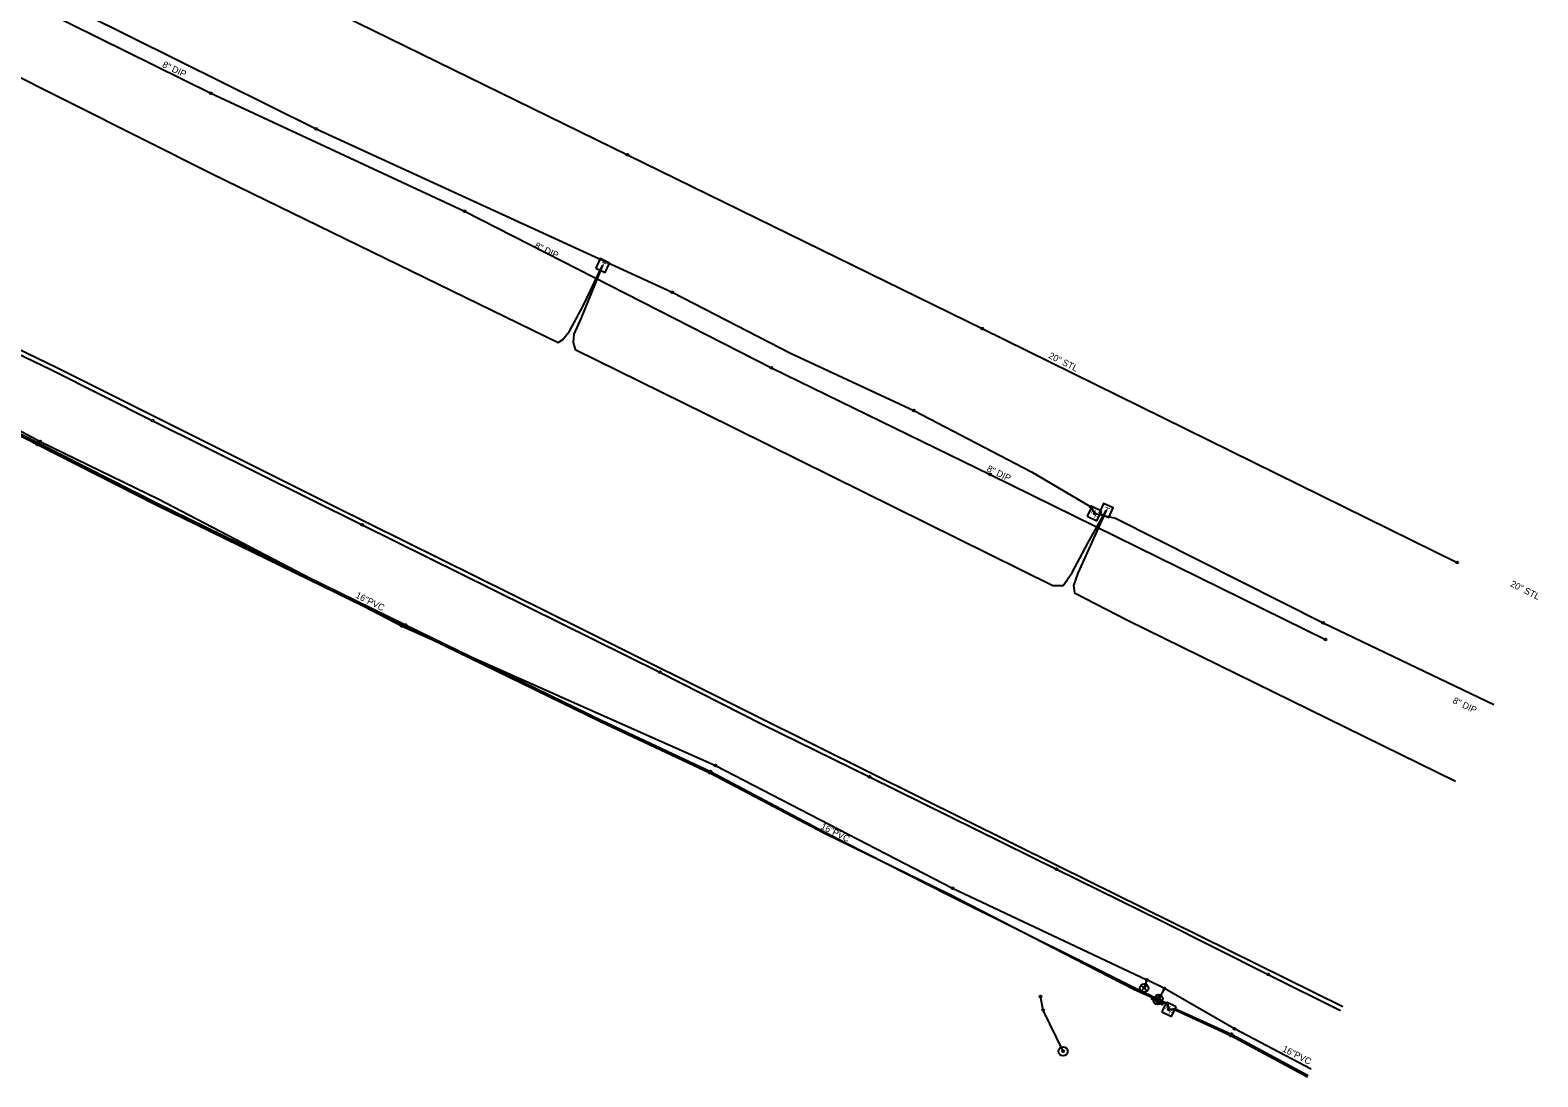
# Model space of a CAD drawing. Extents: x 2244485 to 2250986, y 199568 to 203007.
# Drawn here: x 2250182 to 2250986, y 199568 to 200126 of the extents above; entities that cross this region are included whole.
import ezdxf

# ---------------------------------------------------------------- set-up
doc = ezdxf.new("R2010")
doc.units = 0
for name, color, linetype in [('Default', 7, 'Continuous'), ('Exist Utilities Gas UG Line SUE LOS B', 7, 'Continuous'), ('Exist Utilities Gas UG Line SUE LOS B Text', 7, 'Continuous'), ('Exist Utilities Other Pole CELL', 7, 'Continuous'), ('Exist Utilities Power UG Cable SUE LOS B', 7, 'Continuous'), ('Exist Utilities Sanitary Sewer Forced Main SUE LOS B', 7, 'Continuous'), ('Exist Utilities Sanitary Sewer Forced Main SUE LOS B Text', 7, 'Continuous'), ('Exist Utilities Telephone Hand Hole CELL', 7, 'Continuous'), ('Exist Utilities Telephone Pedestal CELL', 7, 'Continuous'), ('Exist Utilities Telephone UG Cable SUE LOS C', 7, 'Continuous'), ('Exist Utilities Telephone UG FO SUE LOS B', 7, 'Continuous'), ('Exist Utilities Telephone UG FO SUE LOS C', 7, 'Continuous'), ('Exist Utilities Water Fire Hydrant CELL', 7, 'Continuous'), ('Exist Utilities Water UG Line SUE LOS B', 7, 'Continuous'), ('Exist Utilities Water UG Line SUE LOS B Text', 7, 'Continuous'), ('Exist Utilities Water Valve CELL', 7, 'Continuous')]:
    doc.layers.add(name, color=color, linetype=linetype)

# ---------------------------------------------------------------- blocks, each defined once
blk = doc.blocks.new('SurveyPointCell')
at = {"layer": 'Default'}
for p, q in [((-0.5, 0), (0.5, 0)), ((0, -0.5), (0, 0.5))]:
    blk.add_line(p, q, dxfattribs=at)
blk.add_circle((0, 0), 0.5, dxfattribs=at)

msp = doc.modelspace()

# ---------------------------------------------------------------- linework, layer by layer
at = {"layer": 'Exist Utilities Gas UG Line SUE LOS B'}
msp.add_lwpolyline([(2249287.36, 200663.03), (2249402.68, 200604.16), (2249525.39, 200542.56), (2249637.28, 200487.84), (2249753.55, 200430.72), (2249877.93, 200369.52), (2249979.08, 200317.76), (2250124.48, 200245.55), (2250172.44, 200224.83), (2250356.61, 200130.32), (2250500.51, 200059.93), (2250689.7, 199967.14), (2250942.92, 199842.48)], dxfattribs=at)
at = {"layer": 'Exist Utilities Other Pole CELL'}
msp.add_circle((2250732.8, 199581.7), 2.46, dxfattribs=at)
at = {"layer": 'Exist Utilities Power UG Cable SUE LOS B'}
msp.add_lwpolyline([(2250732.85, 199581.76), (2250722.22, 199603.73), (2250720.73, 199610.94)], dxfattribs=at)
at = {"layer": 'Exist Utilities Sanitary Sewer Forced Main SUE LOS B'}
msp.add_lwpolyline([(2249217.76, 200621.23), (2249370.62, 200544.89), (2249544.88, 200455.15), (2249705.6, 200378.34), (2249875.84, 200294.33), (2250020.48, 200224.47), (2250112.79, 200177.26), (2250158.33, 200152.06), (2250278.35, 200092.68), (2250413.6, 200029.72), (2250577.23, 199946.2), (2250693.92, 199889.36), (2250872.7, 199801.35)], dxfattribs=at)
at = {"layer": 'Exist Utilities Telephone Hand Hole CELL'}
for p, q in [((2250748.13, 199872.28), (2250745.7, 199867.09)), ((2250753.31, 199869.85), (2250748.13, 199872.28)), ((2250745.7, 199867.09), (2250750.89, 199864.67)), ((2250749.51, 199868.47), (2250749.51, 199868.47)), ((2250750.89, 199864.67), (2250753.31, 199869.85)), ((2250787.9, 199607.88), (2250785.43, 199602.72)), ((2250793.06, 199605.41), (2250787.9, 199607.88)), ((2250790.59, 199600.25), (2250793.06, 199605.41)), ((2250785.43, 199602.72), (2250790.59, 199600.25)), ((2250789.24, 199604.06), (2250789.24, 199604.06))]:
    msp.add_line(p, q, dxfattribs=at)
at = {"layer": 'Exist Utilities Telephone Pedestal CELL'}
for p, q in [((2250487.21, 200000.87), (2250487.21, 200000.87)), ((2250755.76, 199870.22), (2250755.76, 199870.22))]:
    msp.add_line(p, q, dxfattribs=at)
for points in [[(2250483.54, 199999.49), (2250488.59, 199997.09), (2250490.99, 200002.14), (2250485.94, 200004.54), (2250483.54, 199999.49)], [(2250752.13, 199868.73), (2250757.25, 199866.48), (2250759.51, 199871.6), (2250754.39, 199873.85), (2250752.13, 199868.73)]]:
    msp.add_lwpolyline(points, dxfattribs=at)
at = {"layer": 'Exist Utilities Telephone UG Cable SUE LOS C'}
msp.add_lwpolyline([(2250126.32, 200126.28), (2250278.97, 200049.73), (2250463.49, 199959.77), (2250466.08, 199961.32), (2250469.53, 199965.87), (2250476.77, 199979), (2250487.21, 200000.87), (2250475.74, 199972.84), (2250471.96, 199964.26), (2250471.55, 199959.69), (2250472.59, 199956.11), (2250541.57, 199922.06), (2250727.39, 199830.08), (2250732.79, 199830.2), (2250737.4, 199836.65), (2250745.95, 199852.74), (2250755.76, 199870.22), (2250740.73, 199836.71), (2250738.31, 199830.15), (2250738.96, 199826.31), (2250767.12, 199811.71), (2250942.02, 199725.84)], dxfattribs=at)
at = {"layer": 'Exist Utilities Telephone UG FO SUE LOS B'}
for points in [[(2249321.49, 200578.44), (2249387.5, 200544.86), (2249454.17, 200513.32), (2249518.8, 200482.82), (2249583.28, 200449.94), (2249649.27, 200415.89), (2249731.67, 200374.67), (2249920.99, 200280.45), (2250071.25, 200205.24), (2250113.04, 200184.93), (2250117.77, 200182.84), (2250185.79, 200147.71), (2250334.49, 200073.65), (2250524.31, 199986.53), (2250587.45, 199954.07), (2250653.24, 199923.49), (2250715.98, 199890.78), (2250747.66, 199872.17), (2250749.65, 199868.58), (2250760.75, 199866.03), (2250871.46, 199810.27), (2250962.45, 199766.7)], [(2249319.08, 200376.82), (2249375.45, 200350.06), (2249435.96, 200321), (2249525.24, 200277.08), (2249685.23, 200197.6), (2249751.73, 200164.33), (2249867.18, 200107.28), (2249992.37, 200042.44), (2250002.65, 200033.19), (2250015.25, 200027.15), (2250029.09, 200026.7), (2250139.17, 199971.22), (2250192.89, 199945.32), (2250247.36, 199918.05), (2250358.97, 199862.45), (2250517.75, 199783.98), (2250572.3, 199756.11), (2250629.61, 199728.08), (2250729.22, 199678.8), (2250785.25, 199651.26), (2250842.24, 199622.75), (2250880.78, 199603.41)], [(2250131.82, 199933.16), (2250185.86, 199905.35), (2250249.2, 199873.15), (2250381.71, 199808.47), (2250486.06, 199757.58), (2250544.49, 199730.3), (2250605.54, 199698), (2250672.27, 199665.57), (2250744.89, 199627.96), (2250770.86, 199614.71), (2250788.19, 199606.96), (2250789.24, 199604.06), (2250792.52, 199603.9), (2250822.24, 199590.14), (2250863.16, 199568.07)], [(2250131.9, 199933.91), (2250186.19, 199906.28), (2250249.75, 199874.04), (2250382.04, 199809.11), (2250486.4, 199758.24), (2250544.76, 199730.96), (2250605.81, 199698.52), (2250671.95, 199664.93), (2250745.08, 199628.5), (2250771.34, 199615.34), (2250788.54, 199607.17), (2250789.15, 199604.03), (2250792.44, 199604.5), (2250822.55, 199590.82), (2250863.47, 199568.85)]]:
    msp.add_lwpolyline(points, dxfattribs=at)
at = {"layer": 'Exist Utilities Telephone UG FO SUE LOS C'}
msp.add_lwpolyline([(2249352.73, 200362.96), (2249442.05, 200319.48), (2249492.68, 200294.13), (2249525.95, 200279.04), (2249648.71, 200218.15), (2249719.19, 200182.58), (2249840.2, 200122.41), (2249994.21, 200045.08), (2250034.19, 200025.56), (2250090.65, 199997.4), (2250196.48, 199946.19), (2250343.78, 199872.69), (2250476.54, 199806.8), (2250567.69, 199761.35), (2250630.72, 199730.05), (2250730.23, 199680.67), (2250881.91, 199605.67)], dxfattribs=at)
at = {"layer": 'Exist Utilities Water Fire Hydrant CELL'}
msp.add_line((2250783.07, 199608.58), (2250783.07, 199608.58), dxfattribs=at)
for points in [[(2250781.67, 199609.98), (2250780.56, 199610.63), (2250780.04, 199609.74), (2250781.18, 199609.08)], [(2250784.47, 199609.97), (2250785.12, 199611.09), (2250784.23, 199611.6), (2250783.59, 199610.49)], [(2250784.98, 199608.06), (2250786.09, 199607.41), (2250785.58, 199606.53), (2250784.44, 199607.19)]]:
    msp.add_lwpolyline(points, dxfattribs=at)
for radius in [1.98, 0.243]:
    msp.add_circle((2250783.07, 199608.58), radius, dxfattribs=at)
at = {"layer": 'Exist Utilities Water UG Line SUE LOS B'}
msp.add_line((2250777.46, 199619.82), (2250777.46, 199619.82), dxfattribs=at)
for points in [[(2249895.12, 200055.15), (2249960.22, 200021.32), (2250046.31, 199980.22), (2250134.08, 199935.34), (2250187.34, 199906.97), (2250250.6, 199876.16), (2250380.36, 199808.54), (2250547.37, 199734.1), (2250673.91, 199668.64), (2250777.46, 199619.82)], [(2250777.46, 199619.82), (2250776.06, 199615.49)], [(2250786.83, 199615.19), (2250777.46, 199619.82)], [(2250786.83, 199615.19), (2250783.8, 199609.8), (2250783.07, 199608.59)], [(2250865.16, 199572.2), (2250824.24, 199593.74), (2250786.83, 199615.19)]]:
    msp.add_lwpolyline(points, dxfattribs=at)
at = {"layer": 'Exist Utilities Water Valve CELL'}
for points in [[(2250777.62, 199616.97), (2250774.47, 199613.82), (2250776.05, 199615.39), (2250777.62, 199613.82), (2250774.47, 199616.97)], [(2250785.37, 199611.36), (2250782.22, 199608.21), (2250783.8, 199609.79), (2250785.37, 199608.21), (2250782.22, 199611.36)]]:
    msp.add_lwpolyline(points, dxfattribs=at)
for centre in [(2250776.05, 199615.39), (2250783.8, 199609.79)]:
    msp.add_circle(centre, 2.23, dxfattribs=at)

# ---------------------------------------------------------------- block references
at = {"layer": 'Default'}
for p in [(2250278.35, 200092.68), (2250334.49, 200073.65), (2250500.51, 200059.93), (2250413.6, 200029.72), (2250524.31, 199986.53), (2250689.7, 199967.14), (2250577.23, 199946.2), (2250653.24, 199923.49), (2250247.36, 199918.05), (2250185.86, 199905.35), (2250186.19, 199906.28), (2250187.34, 199906.97), (2250693.92, 199889.36), (2250747.66, 199872.17), (2250358.97, 199862.45), (2250749.65, 199868.58), (2250942.92, 199842.48), (2250380.36, 199808.54), (2250381.71, 199808.47), (2250382.04, 199809.11), (2250871.46, 199810.27), (2250872.7, 199801.35), (2250517.75, 199783.98), (2250547.37, 199734.1), (2250544.49, 199730.3), (2250544.76, 199730.96), (2250629.61, 199728.08), (2250729.22, 199678.8), (2250673.91, 199668.64), (2250842.24, 199622.75), (2250776.06, 199615.49), (2250777.46, 199619.82), (2250777.46, 199619.82), (2250786.83, 199615.19), (2250786.83, 199615.19), (2250720.73, 199610.94), (2250783.07, 199608.59), (2250783.8, 199609.8), (2250722.22, 199603.73), (2250789.15, 199604.03), (2250789.21, 199604.01), (2250822.24, 199590.14), (2250822.55, 199590.82), (2250824.24, 199593.74), (2250732.85, 199581.76)]:
    msp.add_blockref('SurveyPointCell', p, dxfattribs=at)

# ---------------------------------------------------------------- texts
at = {"layer": 'Exist Utilities Gas UG Line SUE LOS B Text'}
for p in [(2250724.71, 199951.66), (2250971.02, 199829.95)]:
    msp.add_text('20" STL', height=3.5, rotation=333.09153, dxfattribs=at).set_placement(p)
at = {"layer": 'Exist Utilities Sanitary Sewer Forced Main SUE LOS B Text'}
for p in [(2250252.1, 200106.82), (2250450.67, 200010.23), (2250691.85, 199891.29), (2250940.29, 199767.61)]:
    msp.add_text('8" DIP', height=3.5, rotation=334.4319, dxfattribs=at).set_placement(p)
at = {"layer": 'Exist Utilities Telephone Hand Hole CELL'}
for rotation, p in [(334.94334, (2250747.37, 199868.82)), (334.94334, (2250749.08, 199866.4)), (334.45041, (2250787.11, 199604.43)), (334.45041, (2250788.8, 199602))]:
    msp.add_text('H', height=2.5, rotation=rotation, dxfattribs=at).set_placement(p)
at = {"layer": 'Exist Utilities Telephone Pedestal CELL'}
for rotation, p in [(334.52409, (2250485.45, 199999.81)), (336.2311, (2250754.04, 199869.11))]:
    msp.add_text('T', height=3.42, rotation=rotation, dxfattribs=at).set_placement(p)
at = {"layer": 'Exist Utilities Water UG Line SUE LOS B Text'}
for p in [(2250355.13, 199823.84), (2250603.23, 199700.58), (2250849.4, 199581.87)]:
    msp.add_text('16"PVC', height=3.5, rotation=333.09153, dxfattribs=at).set_placement(p)

doc.saveas('drawing.dxf')
